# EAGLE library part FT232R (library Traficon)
USB UART IC
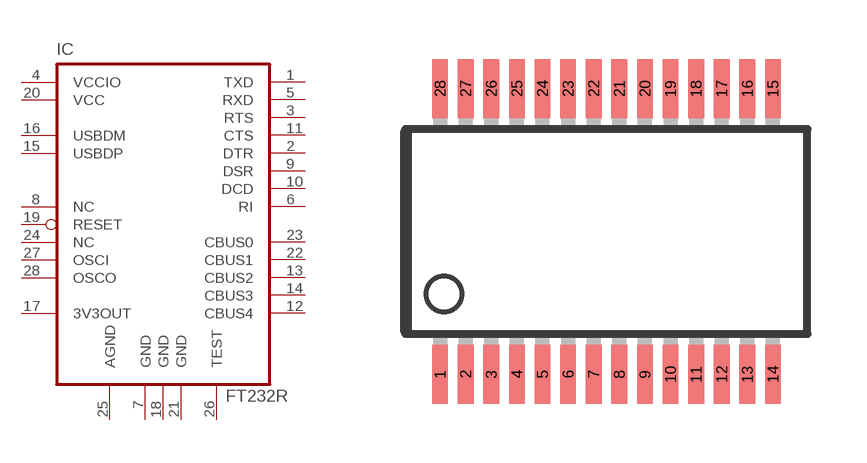
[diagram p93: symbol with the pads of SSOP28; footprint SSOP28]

Designator prefix IC

## FT232R  [SSOP28]
1  TXD
2  DTR
3  RTS
4  VCCIO
5  RXD
6  RI
7  GND
8  NC  nc
9  DSR
10  DCD
11  CTS
12  CBUS4
13  CBUS2
14  CBUS3
15  USBDP
16  USBDM
17  3V3OUT
18  GND
19  RESET
20  VCC
21  GND
22  CBUS1
23  CBUS0
24  NC  nc
25  AGND
26  TEST
27  OSCI
28  OSCO

## Footprint SSOP28 (pad centres in mm)
Shrink Small Outline Package package type SS
smd 0.4 x 1.5: 1 -4.225,-3.625; 2 -3.575,-3.625; 3 -2.925,-3.625; 4 -2.275,-3.625; 5 -1.625,-3.625; 6 -0.975,-3.625; 7 -0.325,-3.625; 8 0.325,-3.625; 9 0.975,-3.625; 10 1.625,-3.625; 11 2.275,-3.625; 12 2.925,-3.625; 13 3.575,-3.625; 14 4.225,-3.625; 15 4.225,3.625; 16 3.575,3.625; 17 2.925,3.625; 18 2.275,3.625; 19 1.625,3.625; 20 0.975,3.625; 21 0.325,3.625; 22 -0.325,3.625; 23 -0.975,3.625; 24 -1.625,3.625; 25 -2.275,3.625; 26 -2.925,3.625; 27 -3.575,3.625; 28 -4.225,3.625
